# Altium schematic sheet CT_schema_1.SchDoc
size 456 x 258 mm
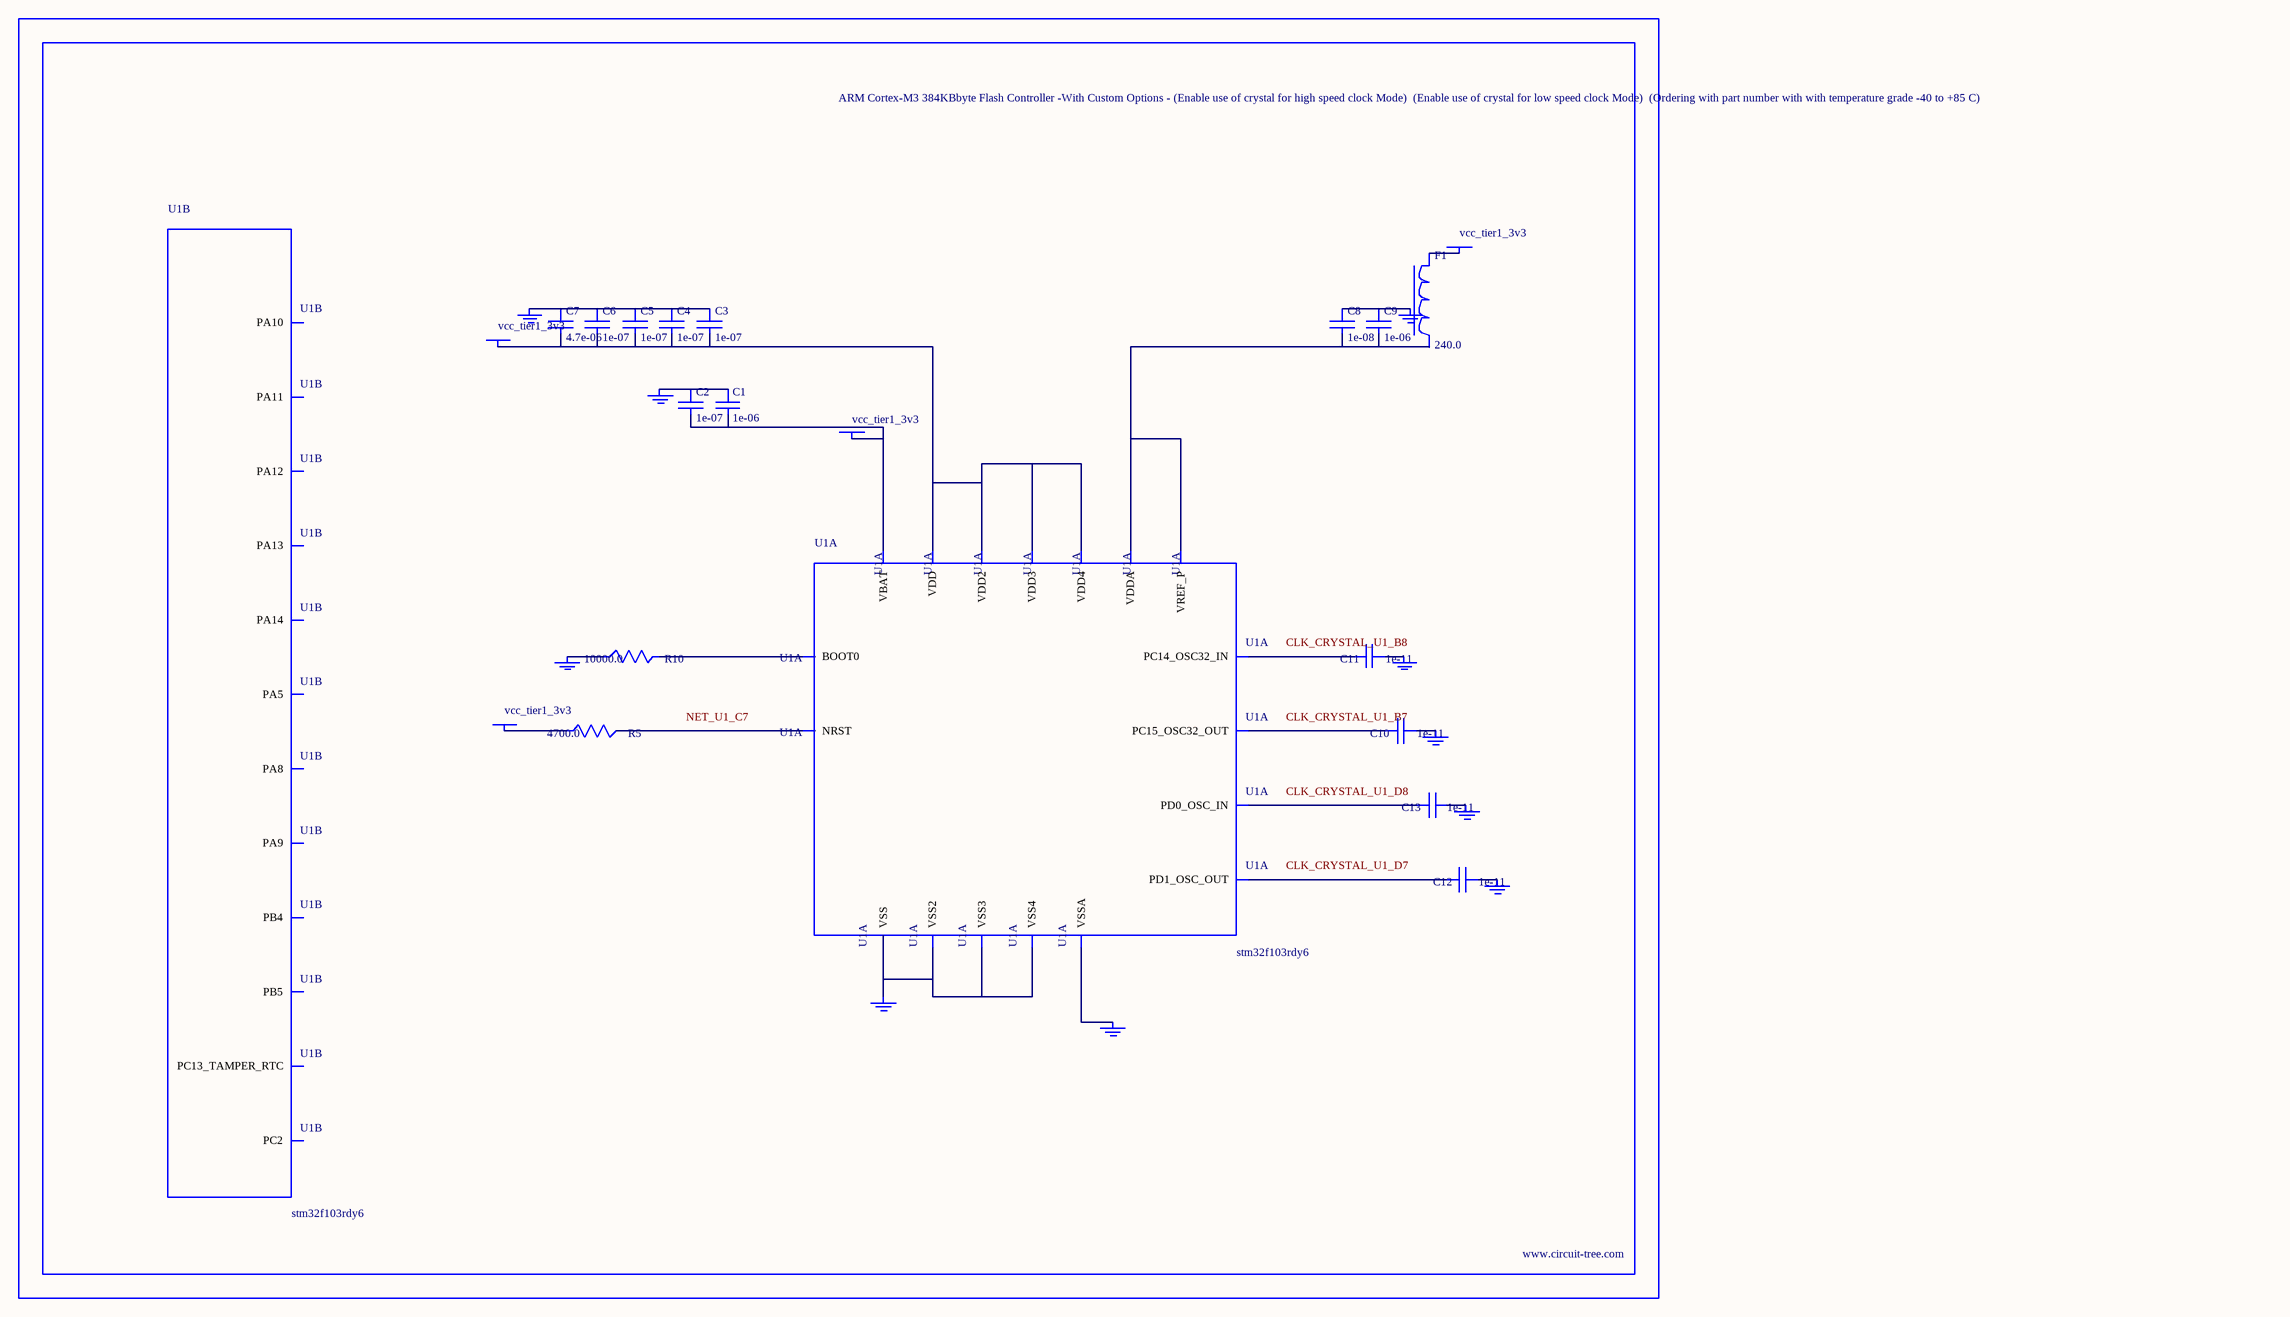
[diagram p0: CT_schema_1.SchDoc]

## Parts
BORDER0  (no value)
C1  1e-06  [C0603]
C2  1e-07  [C0603]
C3  1e-07  [C0603]
C4  1e-07  [C0603]
C5  1e-07  [C0603]
C6  1e-07  [C0603]
C7  4.7e-06  [C0603]
C8  1e-08  [C0603]
C9  1e-06  [C0603]
C10  1e-11  [C0402]
C11  1e-11  [C0402]
C12  1e-11  [C0402]
C13  1e-11  [C0402]
F1  240.0  [L0603]
GND_INSTANCE_0_0  (no value)
GND_INSTANCE_0_1  (no value)
GND_INSTANCE_0_2  (no value)
GND_INSTANCE_0_3  (no value)
GND_INSTANCE_0_4  (no value)
GND_INSTANCE_0_5  (no value)
GND_INSTANCE_0_6  (no value)
GND_INSTANCE_0_7  (no value)
GND_INSTANCE_0_8  (no value)
GND_INSTANCE_0_9  (no value)
POWER_INSTANCE_0_0  vcc_tier1_3v3
POWER_INSTANCE_0_1  vcc_tier1_3v3
POWER_INSTANCE_0_2  vcc_tier1_3v3
POWER_INSTANCE_0_3  vcc_tier1_3v3
R5  4700.0  [R0603]
R10  10000.0  [R0603]
U1  stm32f103rdy6  [WLCSP64]  (parts A,B of 7)

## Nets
NetC1_1: C1.1 C2.1 GND_INSTANCE_0_0.0(GND)
NetC1_2: C1.2 C2.2 POWER_INSTANCE_0_0.0(PWR) U1.C6(VBAT)
NetC3_1: C3.1 C4.1 C5.1 C6.1 C7.1 GND_INSTANCE_0_2.0(GND)
NetC3_2: C3.2 C4.2 C5.2 C6.2 C7.2 POWER_INSTANCE_0_2.0(PWR) U1.A1(VDD) U1.A8(VDD2) U1.G6(VDD3) U1.H1(VDD4)
NetC8_1: C8.1 C9.1 GND_INSTANCE_0_1.0(GND)
NetC8_2: C8.2 C9.2 U1.F7(VREF_P) U1.G8(VDDA)
NetC10_1: C10.1 GND_INSTANCE_0_4.0(GND)
NetC10_2: C10.2 U1.B7(PC15_OSC32_OUT)
NetC11_1: C11.1 GND_INSTANCE_0_5.0(GND)
NetC11_2: C11.2 U1.B8(PC14_OSC32_IN)
NetC12_1: C12.1 GND_INSTANCE_0_6.0(GND)
NetC12_2: C12.2 U1.D7(PD1_OSC_OUT)
NetC13_1: C13.1 GND_INSTANCE_0_7.0(GND)
NetC13_2: C13.2 U1.D8(PD0_OSC_IN)
NetF1_1: F1.1 POWER_INSTANCE_0_1.0(PWR)
NetGND_INSTANCE_0_3_0: GND_INSTANCE_0_3.0(GND) R10.1
NetGND_INSTANCE_0_8_0: GND_INSTANCE_0_8.0(GND) U1.E7(VSSA)
NetGND_INSTANCE_0_9_0: GND_INSTANCE_0_9.0(GND) U1.A7(VSS) U1.B1(VSS2) U1.F5(VSS3) U1.H2(VSS4)
NetPOWER_INSTANCE_0_3_0: POWER_INSTANCE_0_3.0(PWR) R5.1
NetR5_2: R5.2 U1.C7(NRST)
NetR10_2: R10.2 U1.A6(BOOT0)

Not connected (* = marked no-connect by the designer): F1 2; U1 A5(PB5) B2(PA14) B4(PB4) C1(PA11) C2(PA12) C8(PC13_TAMPER_RTC) D2(PA9) D3(PA10) D4(PA13) D6(PC2) E4(PA8) E5(PA5)

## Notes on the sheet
- Labels drawn without touching a wire or pin: CLK_CRYSTAL_U1_B7, CLK_CRYSTAL_U1_B8, CLK_CRYSTAL_U1_D7, CLK_CRYSTAL_U1_D8, NET_U1_C7

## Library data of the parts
BORDER0 = BORDER_PAGE0
C1 C9 = C0603C105K3RACTU
C2-C6 = 06035C104K4Z2A
C7 = GRM188R6YA475KE15D
C8 = 06035C103K4Z2A
C10-C13 = C0402C100K3GACTU
F1 = Z0603C241ASMST
GND_INSTANCE_0_0-GND_INSTANCE_0_9 = GND
POWER_INSTANCE_0_0-POWER_INSTANCE_0_3 = PWR
R5 = RC0603JR-074K7L
R10 = RC0603JR-0710KL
